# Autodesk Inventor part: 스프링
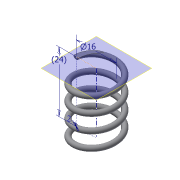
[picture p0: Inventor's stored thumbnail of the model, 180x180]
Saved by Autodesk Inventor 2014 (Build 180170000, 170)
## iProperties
Created: 2015-04
Part Number: 스프링
Material: Generic
Document SubType Name: Modeling
Designer: Administrator
Density: 1 g/cm^3
Appearance: Default
Mass: 0.608323 g
Surface Area: 12.5242 cm^2
Volume: 0.608323 cm^3
Author: Administrator
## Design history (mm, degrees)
sketch "스케치1"
  geometry: L1 (0, 0)-(-8, 0); L2 (-8, 0)-(-8, 11.5); L3 (-8, 11.5)-(0, 11.5); L4 (0, 11.5)-(0, 0); C1 r 1 at (-8, 0)
  constraints: 8 end point, 2 parallel, 1 centre point, 1 coincident, 1 horizontal, 1 perpendicular
  dimensions: "d1" = 16 diameter of L2 L4; "d2" = 11.50049 distance between parallel lines of L3 L1 (derived); "d3" = 2 diameter of C1
feature "코일1" pitch "d4" = 10; turns "d6" = 4; dims "d5" = 11.50049 (= d2), "d7" = 0, angle "d8" = 90 deg, angle "d9" = 90 deg, "d10" = 0, "d11" = 0
sketch "스케치2"
  geometry: L1 (9, 0)-(7, 0) reference; 1 further point
  constraints: 1 horizontal alignment
extrude "돌출1" cut sketch "스케치2" stored distance "d12" = 10; taper "d13" = 0 deg
node "작업 평면1"
sketch "스케치4"
  geometry: L1 (-9, 0)-(-7, 0) reference; 1 further point
  constraints: 1 horizontal alignment
extrude "돌출2" cut sketch "스케치4" stored distance "d14" = 10; taper "d15" = 0 deg
node "솔리드1"
node "절단 모서리 투영1"
node "절단 모서리 투영2"
